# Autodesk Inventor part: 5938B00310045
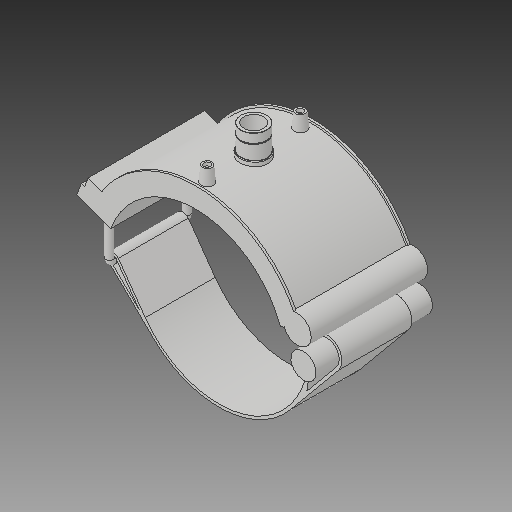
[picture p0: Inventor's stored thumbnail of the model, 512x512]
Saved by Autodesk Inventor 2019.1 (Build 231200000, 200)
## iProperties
Created: 2017-07
Part Number: 5938B00310045
Material: Generic
Description: PLASSON TRANSITION SADDLE 10''IPS x 1"NPT
Document SubType Name: Modeling
Designer: KIM
Density: 1 g/cm^3
Appearance: Default
Author: KIM
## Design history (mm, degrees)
derived "5938B.ipt"
feature "Solid1::5938B.ipt"
tag "TaggingFeature1"
body "Solid1"
other parameters: "d0" = 272.7, "d1" = 327.24, "d2" = 450.85, "d3" = 68.175, "d4" = 176.022, "d5" = 0, "d40" = 170.1648, "d41" = 42.4074, "d43" = 0, "d45" = 0, "d47" = 205.53, "d48" = 39.3783, "d50" = 0, "d78" = 185.62, "d79" = 15, "d80" = 70.4088, "d82" = 5 deg, "d84" = 4, "d85" = 14, "d86" = 0, "d87" = 3, "d88" = 0, "d96" = 333.7848, "d97" = 3.52044, "d98" = 0, "d102" = 0.90873, "d103" = 30.291, "d104" = 25.146, "d105" = 0, "d106" = 24.2328, "d108" = 0, "d109" = -13.97, "d111" = 0.5, "d112" = 0.5, "d113" = 0, "d114" = 0.5, "d117" = 0.30291, "d120" = 140 deg, "d121" = 24.228, "d122" = 20 deg, "d123" = 1308.96, "d124" = 196.344, "d126" = 0, "d143" = 280.881, "d145" = 41.95385, "d149" = 4.0905, "d150" = 46.14923, "d153" = 176.022, "d154" = 0, "d156" = 163.62, "d157" = 160 deg, "d159" = 10.908, "d161" = 4.0905, "d162" = 105.6132, "d163" = 0, "d164" = 136.35, "d167" = 27.27, "d168" = 159.62927, "d170" = 4.0905, "d172" = 0, "d173" = 1, "d175" = 136.35, "d176" = 20 deg, "d177" = 19.089, "d178" = 54.54, "d180" = 0, "d183" = 21.816, "d184" = 15.2712, "d185" = 57.20715, "d186" = 57.20715, "d187" = 163.62, "d188" = 16.362, "d189" = 19.089, "d190" = 0, "d191" = 196.344, "d193" = 10.908, "d194" = 5.59035, "d195" = 90 deg, "d197" = 0, "d199" = 0, "d_" = 272.7, "B_" = 180.34, "H_" = 41.91, "L_" = 176.022, "d_t" = 6, "G_" = 30.291, "d148" = 4.0905, "d160" = 4.0905, "d169" = 4.0905, "d192" = 10.908
